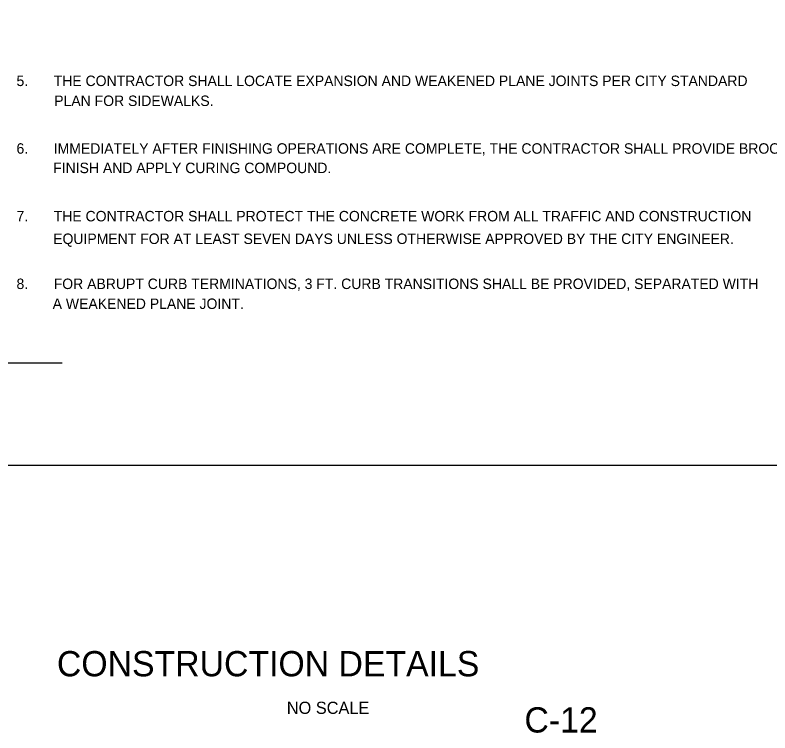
# Model space of a CAD drawing. Extents: x -119017 to -116080, y -104449 to -102845.
# Drawn here: x -118067.3 to -117634.2, y -104448.5 to -104036.8 of the extents above; entities that cross this region are included whole.
import ezdxf

# ---------------------------------------------------------------- set-up
doc = ezdxf.new("R2010")
doc.units = 0
for name, color, linetype in [('Default', 7, 'Continuous'), ('Misc CnstDet(22)', 7, 'Continuous'), ('Nongeo Data(60)', 7, 'Continuous'), ('Sheet Format(10)', 7, 'Continuous')]:
    doc.layers.add(name, color=color, linetype=linetype)

msp = doc.modelspace()

# ---------------------------------------------------------------- linework, layer by layer
at = {"layer": 'Default'}
msp.add_lwpolyline([(-119016.83, -102845.16), (-117223.08, -102845.16), (-117223.08, -104295.16), (-119016.83, -104295.16)], close=True, dxfattribs=at)
at = {"layer": 'Nongeo Data(60)'}
msp.add_line((-118255.04, -104236.34), (-118040.28, -104236.34), dxfattribs=at)

# ---------------------------------------------------------------- texts
at = {"layer": 'Misc CnstDet(22)'}
for s, p in [('5.', (-118066.52, -104077.52)), ('THE CONTRACTOR SHALL LOCATE EXPANSION AND WEAKENED PLANE JOINTS PER CITY STANDARD', (-118045.16, -104077.52)), ('PLAN FOR SIDEWALKS.', (-118044.86, -104088.96)), ('6.', (-118066.52, -104116.33)), ('IMMEDIATELY AFTER FINISHING OPERATIONS ARE COMPLETE, THE CONTRACTOR SHALL PROVIDE BROOM', (-118045.16, -104116.33)), ('FINISH AND APPLY CURING COMPOUND.', (-118045.47, -104127.46)), ('7.', (-118066.52, -104155.14)), ('THE CONTRACTOR SHALL PROTECT THE CONCRETE WORK FROM ALL TRAFFIC AND CONSTRUCTION', (-118045.16, -104155.14)), ('EQUIPMENT FOR AT LEAST SEVEN DAYS UNLESS OTHERWISE APPROVED BY THE CITY ENGINEER.', (-118045.47, -104168.11)), ('8.', (-118066.52, -104193.95)), ('FOR ABRUPT CURB TERMINATIONS, 3 FT. CURB TRANSITIONS SHALL BE PROVIDED, SEPARATED WITH', (-118045.16, -104193.95)), ('A WEAKENED PLANE JOINT.', (-118045.77, -104205.38))]:
    msp.add_text(s, height=6, dxfattribs=at).set_placement(p)
at = {"layer": 'Sheet Format(10)'}
for s, p in [('CONSTRUCTION DETAILS', (-118043.32, -104416.09)), ('C-12', (-117775.06, -104448.33))]:
    msp.add_text(s, height=14.5, dxfattribs=at).set_placement(p)
msp.add_text('NO SCALE', height=7, rotation=0, dxfattribs=at).set_placement((-117911.41, -104437.64))

doc.saveas('drawing.dxf')
